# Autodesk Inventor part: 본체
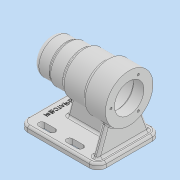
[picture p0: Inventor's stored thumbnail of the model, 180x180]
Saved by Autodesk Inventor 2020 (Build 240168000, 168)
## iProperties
Created: 2021-10
Part Number: 본체
Material: 일반
Document SubType Name: Modeling
Designer: user
Density: 1 g/cm^3
Appearance: 기본값
Author: user
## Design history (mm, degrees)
sketch "스케치1"
  geometry: L1 (0, 0)-(112, 0); L2 (0, 0)-(0, 25); L3 (0, 25)-(24, 25); L4 (24, 25)-(24, 27); L5 (24, 27)-(46, 27); L6 (46, 27)-(46, 30); L7 (46, 30)-(80, 30); L8 (80, 30)-(80, 34); L9 (80, 34)-(112, 34); L10 (6, 0)-(6, 7.5); L11 (9, 10.5)-(9, 10.5); L12 (9, 10.5)-(9, 15.7); L13 (9.3, 16)-(13, 16); L14 (13, 16)-(13, 17.2); L15 (13.3, 17.5)-(31, 17.5); L16 (31, 17.5)-(31, 20.7); L17 (31.3, 21)-(43, 21); L18 (46, 24)-(94, 24); L19 (112, 34)-(112, 21); L20 (97, 21)-(112, 21); A1 r 3 centre (9, 7.5) between (9, 10.5) and (6, 7.5); A2 r 0.3 centre (9.3, 15.7) between (9.3, 16) and (9, 15.7); A3 r 0.3 centre (13.3, 17.2) between (13.3, 17.5) and (13, 17.2); A4 r 0.3 centre (31.3, 20.7) between (31.3, 21) and (31, 20.7); A5 r 3 centre (46, 21) between (46, 24) and (43, 21); A6 r 3 centre (94, 21) between (97, 21) and (94, 24); 6 further points; 1 other entity
  constraints: 40 end point, 14 perpendicular, 12 point on circle, 10 point on line, 10 tangent, 6 centre point, 4 horizontal, 3 equal radius, 3 vertical, 2 vertical alignment, 1 collinear, 5 other
  dimensions: "d0" = 112 distance of L1.start L1.end; "d1" = 24 distance between parallel lines of L2 L4; "d2" = 46 distance between parallel lines of L6 L2; "d3" = 80 distance between parallel lines of L8 L2; "d4" = 50 diameter of L3 L1; "d5" = 54 diameter of L5 L1; "d6" = 60 diameter of L7 L1; "d7" = 68 diameter of L9 L1; "d8" = 21 diameter of L11 L1; "d9" = 32 diameter of L13 L1; "d10" = 35 diameter of L15 L1; "d11" = 18 distance between parallel lines of L16 L14; "d12" = 12 dimension on L16; "d15" = 48 diameter of L18 L1; "d16" = 42 diameter of L17 L1; "d72" = 3 radius of A1; "d73" = 0.3 radius of A2; "d74" = 3 radius of A5; "d75" = 15 distance of L20.start L19.end; "d76" = 54 distance of L20.start L17.end; "d94" = 3 distance between parallel lines of L12 L10; "d95" = 4 distance between parallel lines of L14 L12
revolve "회전1" sketch "스케치1" stored, may be unused: angle "d19" = 90 deg
node "작업 평면1"
sketch "스케치2"
  geometry: L1 (-112, 45)-(0, 45); L2 (0, 45)-(0, -45); L3 (0, -45)-(-112, -45); L4 (-112, -45)-(-112, 45); L5 (-112, 45)-(0, -45); L6 (0, 45)-(-112, -45); L7 (-112, 34)-(-112, -34) reference; 3 further points
  constraints: 12 end point, 3 midpoint, 2 parallel, 1 collinear, 1 horizontal, 1 horizontal alignment, 1 perpendicular
  dimensions: "d21" = 90 distance between parallel lines of L1 L3; "d22" = 112 distance between parallel lines of L4 L2
extrude "돌출1" join sketch "스케치2" distance "d23" = 8; taper "d24" = 0 deg
sketch "스케치3"
  geometry: L1 (112, -45)-(112, 45) reference; L2 (104, 4)-(27, 4); L3 (27, 4)-(27, -4); L4 (27, -4)-(104, -4); L5 (104, -4)-(104, 4); L6 (104, 4)-(27, -4); L7 (27, 4)-(104, -4); 4 further points
  constraints: 12 end point, 4 midpoint, 2 horizontal alignment, 2 parallel, 1 horizontal, 1 perpendicular
  dimensions: "d27" = 8 distance between parallel lines of L4 L2; "d29" = 77 distance between parallel lines of L5 L3; "d30" = 8 distance between parallel lines of L1 L5
extrude "돌출2" join sketch "스케치3" stored distance "d31" = 8; taper "d32" = 0 deg
sketch "스케치4"
  geometry: L1 (-41, -8)-(-41, 0) reference; L2 (-41, 0)-(0, 0) reference; L3 (0, 0)-(0, 28.236) reference; L4 (8, 28.236)-(8, 0) reference; L5 (8, 0)-(49, 0) reference; L6 (49, 0)-(49, -8) reference; L7 (49, -8)-(-41, -8) reference; L8 (0, 0)-(8, 0) reference; L9 (-19.409, 37.342)-(-33, 0); L10 (49, 0)-(-41, 0) reference; L11 (27.409, 37.342)-(41, 0); C1 r 21 at (4, 62) reference; A1 r 34 centre (4, 62) between (8, 28.236) and (0, 28.236) reference; A2 r 34 centre (4, 62) between (0, 28.236) and (8, 28.236) reference; 3 further points
  constraints: 4 end point, 2 point on circle, 2 point on line
  dimensions: "d33" = 8 distance from line of L1 L9.end; "d34" = 110 deg angle of L2 L9; "d35" = 110 deg angle of L5 L11; "d36" = 8 distance of L5.end L11.end
extrude "돌출3" join sketch "스케치4" distance "d37" = 8; taper "d38" = 0 deg
feature "면 기울기1" dims angle "d39" = 15 deg
sketch "스케치7"
  geometry: L1 (20, -33)-(35, -33); L2 (20, -28.5)-(35, -28.5); L3 (35, -37.5)-(20, -37.5); L4 (60, -33)-(75, -33); L5 (60, -37.5)-(75, -37.5); L6 (75, -28.5)-(60, -28.5); L7 (20, 33)-(35, 33); L8 (20, 28.5)-(35, 28.5); L9 (35, 37.5)-(20, 37.5); L10 (60, 33)-(75, 33); L11 (60, 37.5)-(75, 37.5); L12 (75, 28.5)-(60, 28.5); L13 (0, 45)-(0, -45) reference; A1 r 4.5 centre (20, -33) between (20, -28.5) and (20, -37.5); A2 r 4.5 centre (35, -33) between (35, -37.5) and (35, -28.5); A3 r 4.5 centre (60, -33) between (60, -28.5) and (60, -37.5); A4 r 4.5 centre (75, -33) between (75, -37.5) and (75, -28.5); A5 r 4.5 centre (20, 33) between (20, 37.5) and (20, 28.5); A6 r 4.5 centre (35, 33) between (35, 28.5) and (35, 37.5); A7 r 4.5 centre (60, 33) between (60, 37.5) and (60, 28.5); A8 r 4.5 centre (75, 33) between (75, 28.5) and (75, 37.5); 5 further points
  constraints: 32 end point, 16 point on circle, 16 tangent, 8 centre point, 4 horizontal, 4 midpoint, 4 parallel, 2 horizontal alignment
  dimensions: "d40" = 20 distance from line of L1.start L13; "d41" = 15 distance of L1.end L1.start; "d42" = 25 distance of L4.start L1.end; "d43" = 15 distance of L4.end L4.start; "d44" = 33 vertical distance of point (0, 0) point (27.5, -33); "d45" = 20 distance from line of L13 L7.start; "d46" = 15 distance of L7.end L7.start; "d47" = 25 distance of L10.start L7.end; "d48" = 15 distance of L10.end L10.start; "d49" = 9 distance of L3.end L2.start; "d50" = 9 distance of L5.start L6.end; "d51" = 9 distance of L8.start L9.end; "d52" = 9 distance of L12.end L11.start; "d53" = 33 vertical distance of point (0, 0) point (27.5, 33)
extrude "돌출4" cut sketch "스케치7" distance "d54" = 30; taper "d55" = 0 deg
sketch "스케치10"
  geometry: L1 (0, 45)-(0, -45) reference; L2 (0, -45)-(112, -45) reference; 2 further points
  constraints: 1 horizontal alignment, 1 other
  dimensions: "d67" = 12 distance from line of L1 point (12, 0)
feature "엠보싱1" sketch "스케치10" dims "d0" = 112, "d1" = 24, "d2" = 46, "d3" = 80, "d4" = 50, "d5" = 54, "d6" = 60, "d7" = 68, "d8" = 21, "d9" = 32, "d10" = 35, "d11" = 18, "d12" = 12, "d15" = 48, "d16" = 42, "d69" = 0.5, "d70" = 0, "d72" = 3, "d73" = 0.3, "d74" = 3, "d75" = 15, "d76" = 54, "d94" = 3, "d95" = 4
fillet "모깎기1" dims "d71" = 12
sketch "스케치13"
  geometry: 2 further points
  constraints: 1 horizontal alignment
  dimensions: "d77" = 26 distance of point (0, 0) point (-26, 0)
hole "구멍2" sketch "스케치13" at (-26, 0) diameter "d78" = 3.242; stored, may be unused: countersink angle "d82" = 90 deg, drill point angle "d84" = 118 deg; dims "d79" = 8, "d80" = 4, "d81" = 2, "d83" = 11
fillet "모깎기2" dims "d88" = 3
fillet "모깎기3" dims "d89" = 3
fillet "모깎기4" dims "d90" = 3
fillet "모깎기5" dims "d91" = 8
fillet "모깎기6" dims "d92" = 3
fillet "모깎기7" dims "d93" = 3
node "솔리드1"
pattern_circular "원형 패턴2" dims angle "d86" = 360 deg
node "절단 모서리 투영1"
feature "A9D066F2-1C7D-4E18-AEED-F7BC21143FA4" dims "d78" = 3.242, "d79" = 8, "d80" = 4, "d81" = 2, "d82" = 90 deg, "d83" = 11, "d84" = 118 deg
